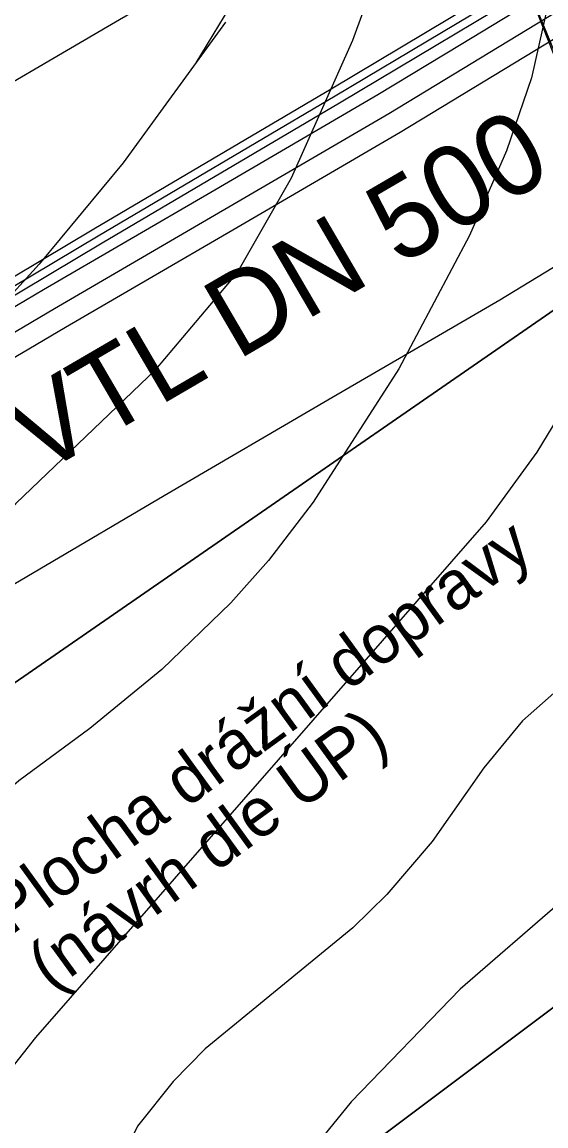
# Model space of a CAD drawing. Extents: x -1900516 to -575031, y -3809306 to -1157387.
# Drawn here: x -577854 to -577757.3, y -1160771.3 to -1160567.5 of the extents above; entities that cross this region are included whole.
import ezdxf

# ---------------------------------------------------------------- set-up
doc = ezdxf.new("R2010")
doc.units = 0
for name, color, linetype in [('01_PARCELY_NÁVRH_PC', 7, 'Continuous'), ('01_PRVKY PRŮZKUMU', 7, 'Continuous'), ('01_VRSTEVNICE', 7, 'Continuous'), ('04_ZPF_OP_ORGAN', 7, 'Continuous'), ('07_OCH_P A POPISY TI', 7, 'Continuous'), ('07_PLYNOVOD', 7, 'Continuous'), ('07_SDĚLOVACÍ', 7, 'Continuous')]:
    doc.layers.add(name, color=color, linetype=linetype)

msp = doc.modelspace()

# ---------------------------------------------------------------- linework, layer by layer
at = {"layer": '01_PARCELY_NÁVRH_PC'}
msp.add_lwpolyline([(-577659.63, -1160774.39), (-577657.84, -1160767.12), (-577655.88, -1160759.15), (-577655.15, -1160726.84), (-577654.47, -1160719.85), (-577665.75, -1160698.09), (-577673.02, -1160685.14), (-577696.47, -1160660.55), (-577725.25, -1160631.4), (-577735.01, -1160617.64), (-577745.19, -1160600.69), (-577762.82, -1160555.81)], dxfattribs=at)
at = {"layer": '01_PRVKY PRŮZKUMU'}
for points in [[(-577117.37, -1160103.48), (-577239.56, -1160208.75), (-577362.02, -1160314.26), (-577478.76, -1160412.02), (-577595.49, -1160509.78), (-577982.6, -1160777.4), (-578055.82, -1160819.76), (-578129.04, -1160862.13), (-578207.65, -1160891.42)], [(-577330.68, -1160401.95), (-577562.75, -1160604.62), (-577673.32, -1160687.49), (-577783.89, -1160770.36), (-577868.87, -1160834.05), (-577953.85, -1160897.74), (-577996.66, -1160944.64), (-578039.47, -1160991.53), (-578074.02, -1161043.54), (-578108.56, -1161095.54), (-578119.26, -1161102.58), (-578129.96, -1161109.61), (-578149.52, -1161114.81), (-578169.09, -1161120.01), (-578207.65, -1160891.42), (-578129.04, -1160862.13), (-578055.82, -1160819.76), (-577982.6, -1160777.4), (-577595.49, -1160509.78), (-577478.76, -1160412.02), (-577362.02, -1160314.26)], [(-578168.03, -1161119.73), (-578149.52, -1161114.81), (-578129.96, -1161109.61), (-578119.26, -1161102.58), (-578108.56, -1161095.54), (-578074.02, -1161043.54), (-578039.47, -1160991.53), (-577996.66, -1160944.64), (-577953.85, -1160897.74), (-577868.87, -1160834.05), (-577783.89, -1160770.36), (-577673.32, -1160687.49), (-577630.01, -1160655.03)]]:
    msp.add_lwpolyline(points, dxfattribs=at)
at = {"layer": '01_VRSTEVNICE'}
for p, q in [((-577812.29, -1160559.13), (-577821.94, -1160575.07)), ((-577816.48, -1160567.56), (-577835.36, -1160593.52)), ((-577835.36, -1160593.52), (-577850.88, -1160612.26)), ((-577850.88, -1160612.26), (-577876.47, -1160640.22))]:
    msp.add_line(p, q, dxfattribs=at)
for points in [[(-578062.57, -1160980.83), (-578051.66, -1160955.38), (-578032.37, -1160918.19), (-578007.06, -1160875.12), (-577999.09, -1160859.46), (-577979.16, -1160806.52), (-577970.43, -1160788.43), (-577957.84, -1160766.62), (-577944.14, -1160746.49), (-577935.75, -1160735.3), (-577917.99, -1160714.33), (-577890.73, -1160687.34), (-577855.21, -1160656.44), (-577829.35, -1160631.7), (-577814.39, -1160613.94), (-577804.32, -1160596.32), (-577792.99, -1160570.87), (-577788.94, -1160559.69), (-577784.19, -1160539.83), (-577781.67, -1160518.02), (-577781.53, -1160489.64), (-577780.13, -1160475.52), (-577772.72, -1160444.2), (-577763.59, -1160415.28)], [(-577755.8, -1160559.13), (-577760, -1160577.86), (-577764.61, -1160591.29), (-577771.46, -1160606.95), (-577784.47, -1160631.55), (-577800.27, -1160656.16), (-577808.52, -1160666.93), (-577815.51, -1160674.76), (-577828.23, -1160687.06), (-577841.51, -1160697.97), (-577854.66, -1160707.62), (-577874.51, -1160724.82), (-577887.93, -1160738.94), (-577898.14, -1160751.52), (-577905.97, -1160764.11), (-577909.46, -1160771.66), (-577924.29, -1160813.32), (-577937.57, -1160853.59), (-577944.98, -1160871.49), (-577950.57, -1160882.67), (-577961.34, -1160900.71), (-577996.85, -1160944.48), (-578003.84, -1160954.54), (-578017.27, -1160977.19)], [(-577738.22, -1160588.57), (-577740.7, -1160606.39), (-577743.78, -1160616.46), (-577748.67, -1160628.2), (-577754.12, -1160638.97), (-577759.02, -1160646.94), (-577768.39, -1160659.8), (-577851.58, -1160755.02), (-577862.35, -1160768.58), (-577869.76, -1160780.32), (-577873.11, -1160787.59), (-577877.17, -1160799.34), (-577889.61, -1160841.29), (-577900.52, -1160873.45), (-577913.1, -1160900.85), (-577919.81, -1160912.59), (-577935.47, -1160932.73), (-577952.11, -1160950.07), (-577967.35, -1160967.27)], [(-577709.29, -1160626.83), (-577716.09, -1160645.12), (-577720.29, -1160653.37), (-577730.08, -1160667.21), (-577738.46, -1160676.02), (-577761.68, -1160696.57), (-577768.8, -1160705.19), (-577778.31, -1160718.8), (-577786.7, -1160728.59), (-577792.99, -1160734.74), (-577820.26, -1160757.11), (-577826.13, -1160763.13), (-577832.7, -1160771.38), (-577837.04, -1160780.32), (-577841.65, -1160793.19), (-577853.68, -1160835.14), (-577859.27, -1160851.91), (-577870.32, -1160881.28), (-577877.45, -1160899.03), (-577891.99, -1160924.48), (-577912.26, -1160955.38), (-577944, -1160998.73)], [(-577687.71, -1160662.18), (-577689.09, -1160667.78), (-577690.93, -1160671.82), (-577696.94, -1160680.77), (-577704.07, -1160688.74), (-577715.25, -1160699.23), (-577754.26, -1160729.71), (-577773.14, -1160746.07), (-577793.28, -1160766.9), (-577806, -1160782.56), (-577811.03, -1160790.67), (-577818.58, -1160808.29), (-577835.36, -1160853.31), (-577842.77, -1160870.93), (-577856.19, -1160900.01), (-577875.21, -1160933.57), (-577893.11, -1160962.65)]]:
    msp.add_lwpolyline(points, dxfattribs=at)
at = {"layer": '04_ZPF_OP_ORGAN'}
msp.add_lwpolyline([(-578186.37, -1160887.36), (-578015.98, -1160834.03), (-577857.15, -1160796.22), (-577700.69, -1160770.14), (-577693.82, -1160702.85), (-577672.15, -1160686.74), (-577673, -1160685.16), (-577725.26, -1160631.39), (-577740.54, -1160609.82), (-577768.95, -1160540.93), (-577841.41, -1160493.17), (-577913.65, -1160368.21), (-577956.7, -1160160.01), (-577999.76, -1159951.82), (-578046.88, -1159720.25)], dxfattribs=at)
msp.add_lwpolyline([(-578186.37, -1160887.36), (-578015.98, -1160834.03), (-577857.15, -1160796.22), (-577700.69, -1160770.14), (-577693.82, -1160702.85), (-577672.15, -1160686.74), (-577673, -1160685.16), (-577725.26, -1160631.39), (-577740.54, -1160609.82), (-577768.95, -1160540.93), (-577841.41, -1160493.17), (-577913.65, -1160368.21), (-577956.7, -1160160.01), (-577999.76, -1159951.82), (-578046.88, -1159720.25)], dxfattribs=at)
at = {"layer": '07_OCH_P A POPISY TI'}
for points in [[(-578095.94, -1160770.91), (-578027.91, -1160732.53), (-577982.61, -1160704.72), (-577934.45, -1160677.91), (-577892.54, -1160651.33), (-577846.04, -1160623.89), (-577815.15, -1160605.87), (-577784.26, -1160587.85), (-577753.57, -1160569.25), (-577735.95, -1160559.14), (-577728.32, -1160555.11), (-577708.17, -1160543.19), (-577596.46, -1160478.05), (-577544.49, -1160447.66), (-577518.11, -1160431.97), (-577490.62, -1160416.86), (-577442.71, -1160390.54), (-577398.17, -1160362.55), (-577335.04, -1160324.25)], [(-578109.27, -1160764.61), (-578065.97, -1160739.17), (-578010.81, -1160706.35), (-577968.04, -1160681.33), (-577914.41, -1160649.67), (-577840.79, -1160605.69), (-577796.99, -1160579.89), (-577757.7, -1160556.37), (-577750.36, -1160552.69), (-577741.91, -1160547.35), (-577731.76, -1160541.04), (-577711.53, -1160529.64), (-577675.25, -1160508.11), (-577599.28, -1160463.37), (-577528.56, -1160421.61), (-577481.48, -1160393.75), (-577448.09, -1160374.33), (-577406.79, -1160350.45), (-577367.23, -1160326.77)], [(-578107.75, -1160767.21), (-578064.45, -1160741.75), (-578009.29, -1160708.93), (-577966.52, -1160683.91), (-577912.87, -1160652.25), (-577839.25, -1160608.27), (-577795.45, -1160582.47), (-577756.26, -1160559.01), (-577748.88, -1160555.31), (-577740.31, -1160549.89), (-577730.24, -1160543.62), (-577710.03, -1160532.24), (-577673.73, -1160510.69), (-577597.76, -1160465.95), (-577527.04, -1160424.19), (-577479.96, -1160396.33), (-577446.59, -1160376.93), (-577405.27, -1160353.03), (-577365.63, -1160329.31)], [(-577806.75, -1160550.03), (-577837.52, -1160567.98), (-577868.3, -1160585.94), (-577891.91, -1160599.87), (-577915.51, -1160613.8), (-577936.23, -1160626.94), (-577956.96, -1160640.08), (-577980.89, -1160653.41), (-578004.83, -1160666.74), (-578027.53, -1160680.67), (-578050.24, -1160694.6), (-578084.15, -1160713.74), (-578118.06, -1160732.87)], [(-578123.05, -1160829.11), (-578077.84, -1160802.03), (-578043.74, -1160782.79), (-578009.64, -1160763.56), (-577987.04, -1160749.68), (-577964.43, -1160735.8), (-577940.24, -1160722.33), (-577916.04, -1160708.86), (-577894.9, -1160695.45), (-577873.76, -1160682.04), (-577850.78, -1160668.49), (-577827.82, -1160654.94), (-577796.84, -1160636.87), (-577765.85, -1160618.79), (-577750.57, -1160609.52), (-577735.28, -1160600.26), (-577718.58, -1160590.68), (-577714.66, -1160588.61), (-577710.73, -1160586.54), (-577690.26, -1160574.42), (-577669.78, -1160562.3)], [(-577757.63, -1160562.35), (-577772.99, -1160571.66), (-577788.34, -1160580.97), (-577819.21, -1160598.98), (-577850.08, -1160616.99), (-577873.4, -1160630.75), (-577896.72, -1160644.51), (-577917.63, -1160657.77), (-577938.55, -1160671.03), (-577962.6, -1160684.42), (-577986.65, -1160697.82), (-578009.31, -1160711.72), (-578031.97, -1160725.63), (-578065.97, -1160744.81), (-578099.96, -1160763.99)]]:
    msp.add_lwpolyline(points, dxfattribs=at)
at = {"layer": '07_PLYNOVOD'}
msp.add_lwpolyline([(-578097.95, -1160767.45), (-578029.94, -1160729.08), (-577984.63, -1160701.27), (-577936.5, -1160674.47), (-577894.63, -1160647.92), (-577848.06, -1160620.44), (-577786.3, -1160584.41), (-577755.6, -1160565.8), (-577737.88, -1160555.64), (-577730.27, -1160551.62), (-577690.05, -1160527.82), (-577624.06, -1160489.28), (-577572.88, -1160459.9), (-577520.1, -1160428.5), (-577465.04, -1160398.25), (-577444.74, -1160387.09), (-577400.28, -1160359.15), (-577354.05, -1160330.96)], dxfattribs=at)
at = {"layer": '07_SDĚLOVACÍ'}
msp.add_lwpolyline([(-578108.51, -1160765.91), (-578065.21, -1160740.46), (-578010.05, -1160707.64), (-577967.28, -1160682.62), (-577913.64, -1160650.96), (-577840.02, -1160606.98), (-577796.22, -1160581.18), (-577756.98, -1160557.69), (-577749.62, -1160554), (-577741.11, -1160548.62), (-577731, -1160542.33), (-577710.78, -1160530.94), (-577674.49, -1160509.4), (-577598.52, -1160464.66), (-577527.8, -1160422.9), (-577480.72, -1160395.04), (-577447.34, -1160375.63), (-577406.03, -1160351.74), (-577366.43, -1160328.04)], dxfattribs=at)
msp.add_lwpolyline([(-578108.51, -1160765.91), (-578065.21, -1160740.46), (-578010.05, -1160707.64), (-577967.28, -1160682.62), (-577913.64, -1160650.96), (-577840.02, -1160606.98), (-577796.22, -1160581.18), (-577756.98, -1160557.69), (-577749.62, -1160554), (-577741.11, -1160548.62), (-577731, -1160542.33), (-577710.78, -1160530.94), (-577674.49, -1160509.4), (-577598.52, -1160464.66), (-577527.8, -1160422.9), (-577480.72, -1160395.04), (-577447.34, -1160375.63), (-577406.03, -1160351.74), (-577366.43, -1160328.04)], dxfattribs=at)

# ---------------------------------------------------------------- texts
at = {"layer": '01_PRVKY PRŮZKUMU'}
for s, p in [('Plocha drážní dopravy', (-577856.15, -1160736.28)), ('(návrh dle ÚP)', (-577848.66, -1160746.6))]:
    msp.add_text(s, height=9, rotation=35.9621, dxfattribs=at).set_placement(p)
at = {"layer": '07_OCH_P A POPISY TI'}
msp.add_text('OP VTL DN 500 (4 m)', height=15, rotation=30.2688, dxfattribs=at).set_placement((-577880.72, -1160668.83))

doc.saveas('drawing.dxf')
